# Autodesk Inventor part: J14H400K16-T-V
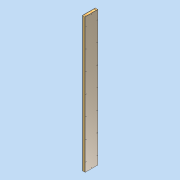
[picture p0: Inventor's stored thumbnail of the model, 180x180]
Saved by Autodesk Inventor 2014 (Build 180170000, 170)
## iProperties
Justset: False
Created: 2012-06
Part Number: J14H400K16-T-V
Document SubType Name: Modeling
Designer: david.appleford
Mass: 144111 g
Surface Area: 120215 cm^2
Volume: 144111 cm^3
Density: 1 g/cm^3
Description: Joist 4w x 400mm 18 Locks - 80mm
Cost Center: £280.00
Material: Generic
Appearance: Default
Author: david.appleford
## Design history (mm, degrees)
sketch "Sketch1"
  geometry: L1 (86, 0)-(86, 400); L2 (0, 400)-(0, 0); L3 (9.1, 356)-(76.9, 356); L4 (77, 400)-(77, 0); L5 (76.9, 44)-(9.1, 44); L6 (9, 0)-(9, 400); L7 (76.9, 355.9)-(9.1, 355.9); L8 (9.1, 44.1)-(76.9, 44.1); L9 (9.1, 400)-(9.1, 356); L10 (76.9, 356)-(76.9, 400); L11 (9.1, 355.9)-(9.1, 44.1); L12 (9.1, 44)-(9.1, 0); L13 (76.9, 0)-(76.9, 44); L14 (76.9, 44.1)-(76.9, 355.9); L15 (0, 0)-(9, 0); L16 (9.1, 0)-(76.9, 0); L17 (77, 0)-(86, 0); L18 (9, 400)-(0, 400); L19 (86, 400)-(77, 400); L20 (76.9, 400)-(9.1, 400)
  constraints: 40 end point, 22 parallel, 8 collinear, 7 perpendicular, 4 horizontal
  dimensions: "d1" = 86 distance between parallel lines of L1 L2; "d4" = 9 distance between parallel lines of L6 L2; "d5" = 9 distance between parallel lines of L1 L4; "d6" = 0.1 distance between parallel lines of L7 L3; "d7" = 0.1 distance between parallel lines of L9 L6; "d8" = 0.1 distance between parallel lines of L4 L10; "d9" = 0.1 distance between parallel lines of L5 L8; "d10" = 400 distance between parallel lines of L15 L18; "d11" = 44 distance between parallel lines of L3 L19; "d13" = 44 distance between parallel lines of L17 L5
extrude "Extrusion1" new body sketch "Sketch1" distance "d14" = 4202; taper "d15" = 0 deg
sketch "Sketch2" dims "d26" = 10
  geometry: L1 (0, 400)-(-4202, 400) reference; L2 (0, 0)-(-4202, 0) reference; L3 (34, 560.068)-(34, -205.63); L4 (-4236, 560.068)-(-4236, -205.63); L5 (0, 400)-(0, 0) reference; L6 (-4202, 400)-(-4202, 0) reference; 16 further points
  constraints: 4 end point, 1 horizontal, 1 horizontal alignment, 1 vertical alignment, 12 other
  dimensions: "d16" = 28 distance from line of L1 point (-271, 372); "d17" = 28 distance from line of L2 point (-271, 28) (= d16); "d18" = 34 distance between parallel lines of L5 L3; "d19" = 4270 distance between parallel lines of L4 L3; "d20" = 305 distance from line of point (-271, 372) L3; "d23" = 610 distance of point (-271, 372) point (-881, 372); "d35" = 28 distance from line of point (-4174, 200) L6 (= d16); "d36" = 28 distance from line of point (-28, 200) L5 (= d16); "d37" = 200 distance from line of point (-4174, 200) L1 (= 0.5 x d38); "d38" = 400 distance between parallel lines of L2 L1 (derived)
hole "Hole1" sketch "Sketch2" at (-271, 28), (-271, 372), (-881, 372), (-881, 28), (-1491, 372), (-1491, 28), (-2101, 372), (-2101, 28), (-2711, 372), (-2711, 28), (-3321, 372), (-3321, 28)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 diameter "d28" = 13; stored, may be unused: countersink angle "d32" = 90 deg, drill point angle "d34" = 118 deg; dims "d29" = 6, "d30" = 4, "d31" = 2, "d33" = 20
body "Solid1"
other parameters: "d0" = 397, "d2" = 44, "d3" = 44
